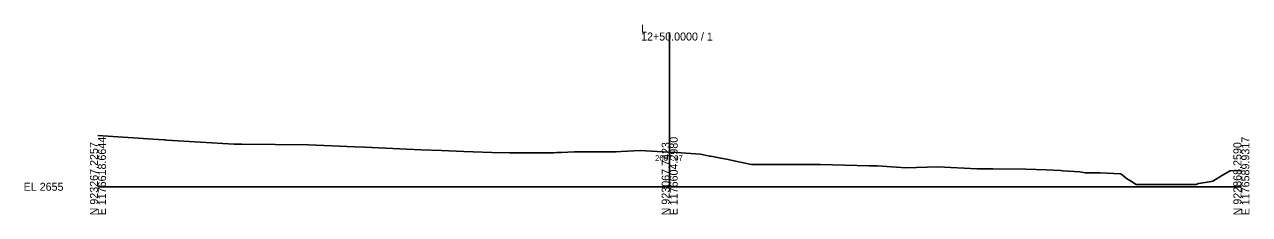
# Model space of a CAD drawing. Extents: x -26 to 1403, y -10 to 9563.
# Drawn here: x -25.7 to 402.8, y 2490.3 to 2556.7 of the extents above; entities that cross this region are included whole.
import ezdxf

# ---------------------------------------------------------------- set-up
doc = ezdxf.new("R2010")
doc.units = 0
for name, color, linetype in [('Exist Cross Section Cell', 7, 'Continuous'), ('Exist XS Center Line Elevation Label', 7, 'Continuous'), ('Exist XS Ground Line', 7, 'Continuous')]:
    doc.layers.add(name, color=color, linetype=linetype)

msp = doc.modelspace()

# ---------------------------------------------------------------- linework, layer by layer
at = {"layer": 'Exist Cross Section Cell'}
for p, q in [((200, 2500), (200, 2553.94)), ((0, 2500), (200, 2500)), ((200, 2500), (400, 2500))]:
    msp.add_line(p, q, dxfattribs=at)
at = {"layer": 'Exist XS Ground Line'}
for p, q in [((0, 2517.98), (19.33, 2516.66)), ((19.33, 2516.66), (23.01, 2516.41)), ((23.01, 2516.41), (23.47, 2516.37)), ((23.47, 2516.37), (24.15, 2516.33)), ((24.15, 2516.33), (47.67, 2514.88)), ((47.67, 2514.88), (50.33, 2514.85)), ((50.33, 2514.85), (73.61, 2514.71)), ((73.61, 2514.71), (89.82, 2513.99)), ((89.82, 2513.99), (93.33, 2513.87)), ((93.33, 2513.87), (108.04, 2513.19)), ((108.04, 2513.19), (113.07, 2512.94)), ((113.07, 2512.94), (120.23, 2512.69)), ((120.23, 2512.69), (127.97, 2512.37)), ((127.97, 2512.37), (137.81, 2511.99)), ((137.81, 2511.99), (144.07, 2511.82)), ((144.07, 2511.82), (156.94, 2511.89)), ((156.94, 2511.89), (158.61, 2511.87)), ((158.61, 2511.87), (159.47, 2511.91)), ((159.47, 2511.91), (160.48, 2511.96)), ((160.48, 2511.96), (162.2, 2512.03)), ((162.2, 2512.03), (166.61, 2512.23)), ((166.61, 2512.23), (172.59, 2512.2)), ((172.59, 2512.2), (175.15, 2512.2)), ((175.15, 2512.2), (181.32, 2512.18)), ((181.32, 2512.18), (182.98, 2512.28)), ((182.98, 2512.28), (189.63, 2512.68)), ((189.63, 2512.68), (191.71, 2512.55)), ((191.71, 2512.55), (199.7, 2512.09)), ((199.7, 2512.09), (202.38, 2511.93)), ((202.38, 2511.93), (210.83, 2511.44)), ((210.83, 2511.44), (213.94, 2510.76)), ((213.94, 2510.76), (214.45, 2510.67)), ((214.45, 2510.67), (217.93, 2510.04)), ((217.93, 2510.04), (219.88, 2509.7)), ((219.88, 2509.7), (223.63, 2508.89)), ((223.63, 2508.89), (228.05, 2507.87)), ((228.05, 2507.87), (228.57, 2507.81)), ((228.57, 2507.81), (229.01, 2507.81)), ((229.01, 2507.81), (245.41, 2507.77)), ((245.41, 2507.77), (247.21, 2507.77)), ((247.21, 2507.77), (248.42, 2507.76)), ((248.42, 2507.76), (252.76, 2507.77)), ((252.76, 2507.77), (269.77, 2507.37)), ((269.77, 2507.37), (272.69, 2507.29)), ((272.69, 2507.29), (274.34, 2507.23)), ((274.34, 2507.23), (282.65, 2506.63)), ((282.65, 2506.63), (293.87, 2507.01)), ((293.87, 2507.01), (307.62, 2506.26)), ((307.62, 2506.26), (313.08, 2506.22)), ((313.08, 2506.22), (324.55, 2506.12)), ((324.55, 2506.12), (331.73, 2505.98)), ((331.73, 2505.98), (336.77, 2505.68)), ((336.77, 2505.68), (337.51, 2505.63)), ((337.51, 2505.63), (343.47, 2505.23)), ((343.47, 2505.23), (345.32, 2504.92)), ((345.32, 2504.92), (346.82, 2504.89)), ((346.82, 2504.89), (349.28, 2504.9)), ((349.28, 2504.9), (350.55, 2504.83)), ((350.55, 2504.83), (357.78, 2504.57)), ((357.78, 2504.57), (360.15, 2502.7)), ((360.15, 2502.7), (361.21, 2502.1)), ((389.96, 2502), (393.43, 2504.08)), ((393.43, 2504.08), (396.07, 2505.62)), ((396.07, 2505.62), (400, 2505.72)), ((361.21, 2502.1), (363.21, 2500.79)), ((363.21, 2500.79), (374.48, 2500.79)), ((374.48, 2500.79), (384.15, 2500.79)), ((384.15, 2500.79), (384.98, 2501.18)), ((384.98, 2501.18), (388.82, 2501.67)), ((388.82, 2501.67), (389.96, 2502))]:
    msp.add_line(p, q, dxfattribs=at)

# ---------------------------------------------------------------- texts
at = {"layer": 'Exist Cross Section Cell'}
for s, p in [('12+50.0000 / 1', (190, 2551.14)), ('L', (190, 2553.94)), ('EL 2655', (-26, 2498.6))]:
    msp.add_text(s, height=2.8, dxfattribs=at).set_placement(p)
for s, p in [('E 1176618.6644', (2.8, 2490)), ('E 1176604.2980', (202.8, 2490)), ('E 1176589.9317', (402.8, 2490)), ('N 923267.2257', (0, 2490)), ('N 923067.7423', (200, 2490)), ('N 922868.2590', (400, 2490))]:
    msp.add_text(s, height=2.8, rotation=90, dxfattribs=at).set_placement(p)
at = {"layer": 'Exist XS Center Line Elevation Label'}
msp.add_text('2667.07', height=2, dxfattribs=at).set_placement((194.91, 2509.07))

doc.saveas('drawing.dxf')
